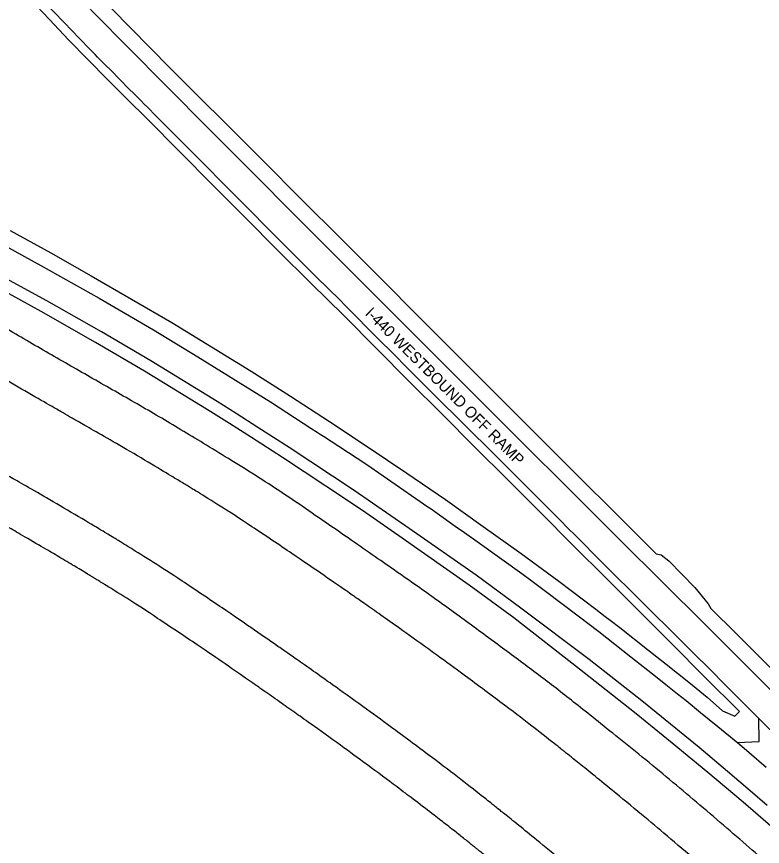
# Model space of a CAD drawing. Extents: x 1729281 to 1732101, y 650763 to 653805.
# Drawn here: x 1730660.8 to 1731062.7, y 652139.3 to 652586.3 of the extents above; entities that cross this region are included whole.
import ezdxf

# ---------------------------------------------------------------- set-up
doc = ezdxf.new("R2010")
doc.units = 0
for name, color, linetype in [('SURVEY - ROADSIDE BARRIERS with Text', 7, 'Continuous'), ('SURVEY - TRAFFIC CONTROL - Pavement Marking with Text', 7, 'Continuous'), ('SURVEY - TRANSPORTATION - Features', 7, 'Continuous'), ('SURVEY - TRANSPORTATION - Roads', 7, 'Continuous'), ('SURVEY - TRANSPORTATION - Roads Text', 7, 'Continuous')]:
    doc.layers.add(name, color=color, linetype=linetype)

msp = doc.modelspace()

# ---------------------------------------------------------------- linework, layer by layer
at = {"layer": 'SURVEY - ROADSIDE BARRIERS with Text'}
for points in [[(1730975.1, 652226.1), (1730964.18, 652234.73), (1730928.69, 652262.46), (1730904.57, 652280.1), (1730868.61, 652305.29), (1730848.9, 652318.94), (1730839.08, 652325.7), (1730804.14, 652348.81), (1730787.34, 652359.55), (1730775.57, 652367.08), (1730765.45, 652373.4), (1730729.72, 652395.29), (1730703.22, 652410.78), (1730673.94, 652427.43), (1730647.79, 652441.74)], [(1731071.12, 652146.74), (1731052.31, 652163.12), (1731033.25, 652179.2), (1731014.06, 652194.99), (1730994.61, 652210.7), (1730975.1, 652226.1)]]:
    msp.add_lwpolyline(points, dxfattribs=at)
at = {"layer": 'SURVEY - TRAFFIC CONTROL - Pavement Marking with Text'}
msp.add_lwpolyline([(1731049.05, 652195.35), (1731060.99, 652195.88), (1731060.77, 652208.25)], dxfattribs=at)
at = {"layer": 'SURVEY - TRANSPORTATION - Features'}
for points in [[(1730701.46, 652601.45), (1730722.34, 652580.03), (1730743.41, 652558.73), (1730764.61, 652537.57), (1730768.16, 652534.04), (1730793.21, 652508.89), (1730814.38, 652487.68), (1730835.6, 652466.49), (1730856.8, 652445.32), (1730878.03, 652424.11), (1730899.19, 652402.83), (1730920.41, 652381.64), (1730941.6, 652360.4), (1730962.88, 652339.27), (1730984.14, 652318.11), (1731005.4, 652296.96), (1731008.07, 652296.35)], [(1731047.73, 652209.41), (1731050.35, 652211.96), (1731031.53, 652230.73), (1731013.81, 652248.35), (1730996.17, 652266.06), (1730978.49, 652283.76), (1730960.75, 652301.37), (1730943.11, 652319.11), (1730925.41, 652336.72), (1730907.68, 652354.36), (1730890.14, 652372.17), (1730872.36, 652389.74), (1730854.71, 652407.49), (1730837.08, 652425.19), (1730819.29, 652442.68), (1730801.53, 652460.32), (1730783.88, 652478), (1730766.28, 652495.73), (1730748.75, 652513.52), (1730731.14, 652531.23), (1730720.44, 652541.73), (1730709.84, 652552.32), (1730699.34, 652563.01), (1730688.84, 652573.77), (1730678.59, 652584.69), (1730668.21, 652595.62)], [(1730657.24, 652471.12), (1730679.15, 652458.96), (1730700.91, 652446.66), (1730722.72, 652434.14), (1730744.45, 652421.45), (1730765.87, 652408.43), (1730787.1, 652395.25), (1730808.36, 652381.81), (1730829.42, 652368.2), (1730850.29, 652354.45), (1730871.15, 652340.34), (1730891.85, 652326.16), (1730912.26, 652311.72), (1730932.62, 652297.09), (1730952.92, 652282.17), (1730972.94, 652267.1), (1730977.98, 652263.09), (1730980.58, 652261.16), (1730985.79, 652257.15), (1731000.69, 652245.44)], [(1731008.07, 652296.35), (1731012.17, 652293.06), (1731026.29, 652278.76), (1731033.43, 652270.02)], [(1731033.43, 652270.02), (1731034.94, 652267.43), (1731048.46, 652253.94), (1731069.69, 652232.73), (1731090.91, 652211.51), (1731112.06, 652190.2), (1731133.28, 652168.97), (1731154.32, 652147.58), (1731175.37, 652126.2), (1731196.37, 652104.63), (1731217.28, 652083.07), (1731237.88, 652061.26), (1731258.4, 652039.18), (1731278.68, 652016.88), (1731284.06, 652009.86), (1731303.09, 651986.57), (1731322.55, 651963.65), (1731341.9, 651940.64), (1731361.11, 651917.48), (1731380.08, 651894.11), (1731398.72, 651870.57), (1731417.16, 651846.86), (1731435.47, 651822.97)], [(1731000.69, 652245.44), (1731010.72, 652237.52), (1731022.93, 652227.87), (1731032.92, 652219.72), (1731041.23, 652212.43), (1731047.73, 652209.41)]]:
    msp.add_lwpolyline(points, dxfattribs=at)
at = {"layer": 'SURVEY - TRANSPORTATION - Roads'}
for points in [[(1730693.2, 652597.85), (1730708.56, 652582.15), (1730715.58, 652575.04), (1730746.5, 652543.82), (1730759.18, 652531.06), (1730771.86, 652518.31), (1730793.02, 652497.08), (1730805.72, 652484.34), (1730831.15, 652458.88), (1730843.88, 652446.17), (1730863.71, 652426.41), (1730875.03, 652415.1), (1730899.04, 652391.04), (1730910.37, 652379.75), (1730935.76, 652354.33), (1730956.03, 652334.21), (1730971.98, 652318.3), (1730987.47, 652302.85), (1731007.33, 652283.11), (1731032.83, 652257.7), (1731045.57, 652244.98), (1731076.7, 652213.89), (1731092.24, 652198.32)], [(1731071.04, 652197.97), (1731062.56, 652206.46), (1731042.76, 652226.26), (1731034.27, 652234.74), (1731025.77, 652243.21), (1731017.24, 652251.66), (1730998.78, 652269.96), (1730976.37, 652292.33), (1730961.86, 652306.79), (1730957.88, 652310.75), (1730953.65, 652315.01), (1730930.88, 652337.88), (1730922.71, 652345.95), (1730897.7, 652370.82), (1730890.15, 652378.3), (1730871.71, 652396.62), (1730863.26, 652405.14), (1730856.22, 652412.24), (1730837.88, 652430.65), (1730835.05, 652433.48), (1730822.24, 652446.11), (1730813.69, 652454.53), (1730799.61, 652468.72), (1730782.71, 652485.73), (1730775.66, 652492.81), (1730758.93, 652509.61), (1730750.7, 652517.88), (1730742.28, 652526.35), (1730742.11, 652526.51), (1730735.25, 652533.42), (1730731.82, 652536.87), (1730729.04, 652539.66), (1730728.88, 652539.83), (1730728.8, 652539.91), (1730728.55, 652540.16), (1730728.39, 652540.32), (1730724.14, 652544.59), (1730721.33, 652547.42), (1730711.49, 652557.35), (1730708.68, 652560.19), (1730707.27, 652561.61), (1730704.46, 652564.45), (1730703.05, 652565.87), (1730701.65, 652567.29), (1730698.83, 652570.12), (1730696.05, 652572.99), (1730694.66, 652574.43), (1730690.5, 652578.73), (1730686.33, 652583.04), (1730675.22, 652594.51)], [(1730649.22, 652465.7), (1730673.76, 652452.23), (1730705.2, 652434.69), (1730734.58, 652417.59), (1730758.51, 652403.05), (1730784.01, 652387.26), (1730797.56, 652378.75), (1730819.41, 652364.67), (1730822.77, 652362.5), (1730824.45, 652361.42), (1730826.12, 652360.32), (1730834.48, 652354.83), (1730849.52, 652344.94), (1730875.87, 652326.79), (1730882.45, 652322.24), (1730884.09, 652321.1), (1730897.16, 652311.88), (1730902.06, 652308.42), (1730910.23, 652302.65), (1730932.95, 652286.29), (1730937.81, 652282.78), (1730945.81, 652276.78), (1730963.37, 652263.53), (1730974.48, 652255.01), (1730991.85, 652241.52), (1731005.94, 652230.32), (1731010.62, 652226.57), (1731016.87, 652221.57), (1731021.55, 652217.83), (1731029.3, 652211.51), (1731038.59, 652203.91), (1731049.42, 652195.05), (1731054.02, 652191.19), (1731055.54, 652189.89), (1731064.63, 652182.06)], [(1731065.18, 652161.42), (1731056.1, 652169.25), (1731043.89, 652179.6), (1731028.64, 652192.53), (1730997.61, 652217.76), (1730969.27, 652239.95), (1730932.57, 652267.67), (1730908.36, 652285.39), (1730872.32, 652310.62), (1730852.59, 652324.29), (1730842.71, 652331.09), (1730807.69, 652354.26), (1730790.84, 652365.03), (1730779.05, 652372.57), (1730768.87, 652378.93), (1730733.06, 652400.86), (1730706.47, 652416.41), (1730677.11, 652433.11), (1730650.89, 652447.45)]]:
    msp.add_lwpolyline(points, dxfattribs=at)
for points in [[(1731531.64, 651585.15), (1731524.94, 651594.88), (1731518.23, 651604.6), (1731511.53, 651614.33), (1731495.84, 651637.09), (1731479.61, 651659.46), (1731463.56, 651681.97), (1731448.09, 651703.66), (1731432.47, 651725.24), (1731416.68, 651746.7), (1731388.71, 651784.72), (1731359.2, 651821.53), (1731329.41, 651858.17), (1731313.35, 651877.92), (1731296.84, 651897.26), (1731279.99, 651916.35), (1731249.08, 651951.38), (1731217.44, 651985.64), (1731184.75, 652019.02), (1731165.49, 652038.69), (1731145.75, 652057.82), (1731125.51, 652076.48), (1731104.49, 652095.86), (1731083.19, 652114.88), (1731061.55, 652133.58), (1731032.69, 652158.51), (1731003.56, 652183.06), (1730973.77, 652206.88), (1730955.05, 652221.83), (1730936, 652236.31), (1730916.71, 652250.52), (1730895.37, 652266.24), (1730873.8, 652281.59), (1730852.02, 652296.7), (1730823.56, 652316.46), (1730794.97, 652335.97), (1730765.4, 652354.03), (1730742.02, 652368.29), (1730718.3, 652381.9), (1730694.53, 652395.48), (1730670.65, 652409.13), (1730646.99, 652423.18), (1730622.57, 652435.85), (1730604.25, 652445.36), (1730585.78, 652454.57), (1730567.34, 652463.85), (1730548.53, 652473.32), (1730529.72, 652482.79), (1730510.84, 652492.11), (1730492.28, 652501.28), (1730473.44, 652509.87), (1730454.35, 652517.88), (1730438.11, 652524.71), (1730421.85, 652531.5), (1730405.58, 652538.25)], [(1731511.88, 651571.53), (1731507.41, 651578.01), (1731500.71, 651587.73), (1731494.01, 651597.45), (1731491.64, 651600.89), (1731491.5, 651601.09), (1731491.23, 651601.49), (1731490.81, 651602.09), (1731489.85, 651603.49), (1731487.91, 651606.28), (1731486.24, 651608.67), (1731476.22, 651623.03), (1731467.12, 651635.76), (1731453.38, 651654.94), (1731448.78, 651661.35), (1731443.62, 651668.6), (1731443.05, 651669.39), (1731441.91, 651670.98), (1731440.2, 651673.38), (1731436.21, 651678.95), (1731423.65, 651696.46), (1731410.99, 651713.9), (1731399.98, 651728.9), (1731398.24, 651731.27), (1731397.07, 651732.85), (1731396.5, 651733.62), (1731393.62, 651737.53), (1731386.67, 651746.88), (1731379.63, 651756.18), (1731365.42, 651774.71), (1731355.8, 651786.99), (1731336.34, 651811.46), (1731326.51, 651823.66), (1731315.38, 651837.38), (1731313.52, 651839.66), (1731311.67, 651841.95), (1731310.43, 651843.47), (1731309.82, 651844.22), (1731306.76, 651847.97), (1731299.37, 651856.96), (1731286.88, 651871.82), (1731276.72, 651883.61), (1731266.49, 651895.37), (1731261.34, 651901.23), (1731245.82, 651918.75), (1731224.93, 651941.93), (1731198.32, 651970.43), (1731179.41, 651990.12), (1731171.24, 651998.51), (1731167.15, 652002.69), (1731165.8, 652004.07), (1731163.07, 652006.84), (1731150.8, 652019.25), (1731138.34, 652031.45), (1731121.48, 652047.47), (1731115.82, 652052.77), (1731108.69, 652059.35), (1731107.25, 652060.68), (1731104.37, 652063.32), (1731100.06, 652067.27), (1731084.2, 652081.72), (1731066.73, 652097.28), (1731052.02, 652110.08), (1731047.6, 652113.91), (1731046.13, 652115.19), (1731043.16, 652117.75), (1731035.75, 652124.14), (1731028.32, 652130.5), (1731010.45, 652145.7), (1730998.49, 652155.74), (1730980.44, 652170.62), (1730971.38, 652178.01), (1730962.28, 652185.34), (1730957.71, 652188.99), (1730956.2, 652190.19), (1730953.17, 652192.6), (1730939.49, 652203.41), (1730925.59, 652214.01), (1730900.64, 652232.62), (1730888.04, 652241.81), (1730869.01, 652255.44), (1730859.46, 652262.22), (1730849.87, 652268.95), (1730843.46, 652273.43), (1730840.26, 652275.65), (1730824.15, 652286.83), (1730811.28, 652295.68), (1730785.46, 652312.97), (1730772.5, 652321.4), (1730757.78, 652330.54), (1730756.14, 652331.55), (1730753.68, 652333.06), (1730752.86, 652333.56), (1730751.2, 652334.57), (1730747.06, 652337.09), (1730736.26, 652343.59), (1730719.49, 652353.47), (1730705.94, 652361.28), (1730695.75, 652367.13), (1730690.65, 652370.06), (1730685.53, 652372.98), (1730682.12, 652374.93), (1730680.39, 652375.92), (1730664.91, 652384.8), (1730651.37, 652392.7), (1730631.13, 652404.05), (1730624.39, 652407.75), (1730615.96, 652412.23), (1730614.27, 652413.11), (1730610.89, 652414.87), (1730609.15, 652415.77), (1730603.96, 652418.45), (1730600.5, 652420.23), (1730590.07, 652425.56), (1730583.08, 652429.08), (1730569.07, 652436.14), (1730562.03, 652439.66), (1730540.91, 652450.27), (1730526.87, 652457.34), (1730509.33, 652466.07), (1730505.83, 652467.82), (1730501.44, 652469.99), (1730500.56, 652470.42), (1730498.83, 652471.28), (1730496.24, 652472.55), (1730486.72, 652477.19), (1730478.03, 652481.28), (1730464.07, 652487.63), (1730457.06, 652490.71), (1730449.14, 652494.05), (1730447.82, 652494.61), (1730446.28, 652495.25), (1730445.62, 652495.52), (1730445.18, 652495.71), (1730444.95, 652495.8), (1730442.91, 652496.65), (1730437.45, 652498.91), (1730423.38, 652504.74), (1730411.12, 652509.82), (1730399.69, 652514.48)], [(1731474.27, 651542.24), (1731469.8, 651548.72), (1731463.1, 651558.44), (1731456.4, 651568.16), (1731454.02, 651571.6), (1731453.89, 651571.8), (1731453.61, 651572.2), (1731453.2, 651572.8), (1731452.23, 651574.19), (1731450.3, 651576.99), (1731448.63, 651579.38), (1731438.6, 651593.74), (1731429.5, 651606.46), (1731415.76, 651625.65), (1731411.17, 651632.06), (1731406, 651639.3), (1731405.44, 651640.1), (1731404.3, 651641.69), (1731402.59, 651644.08), (1731398.6, 651649.66), (1731386.03, 651667.17), (1731373.37, 651684.6), (1731362.36, 651699.61), (1731360.62, 651701.98), (1731359.46, 651703.55), (1731358.89, 651704.33), (1731356.01, 651708.24), (1731349.06, 651717.59), (1731342.01, 651726.88), (1731327.81, 651745.42), (1731318.18, 651757.7), (1731298.73, 651782.17), (1731288.89, 651794.37), (1731277.77, 651808.08), (1731275.91, 651810.37), (1731274.05, 651812.66), (1731272.81, 651814.18), (1731272.21, 651814.93), (1731269.14, 651818.68), (1731261.75, 651827.67), (1731249.26, 651842.53), (1731239.1, 651854.32), (1731228.88, 651866.08), (1731223.73, 651871.94), (1731208.21, 651889.46), (1731187.32, 651912.63), (1731160.7, 651941.14), (1731141.79, 651960.83), (1731133.63, 651969.22), (1731129.54, 651973.4), (1731128.18, 651974.78), (1731125.46, 651977.54), (1731113.19, 651989.96), (1731100.72, 652002.15), (1731083.86, 652018.18), (1731078.2, 652023.48), (1731071.07, 652030.06), (1731069.63, 652031.38), (1731066.76, 652034.02), (1731062.45, 652037.98), (1731046.58, 652052.43), (1731029.12, 652067.98), (1731014.41, 652080.79), (1731009.99, 652084.62), (1731008.51, 652085.9), (1731005.55, 652088.46), (1730998.13, 652094.85), (1730990.7, 652101.21), (1730972.84, 652116.41), (1730960.88, 652126.44), (1730942.82, 652141.33), (1730933.77, 652148.72), (1730924.66, 652156.04), (1730920.1, 652159.69), (1730918.59, 652160.9), (1730915.55, 652163.3), (1730901.87, 652174.12), (1730887.98, 652184.72), (1730863.02, 652203.32), (1730850.42, 652212.51), (1730831.4, 652226.15), (1730821.85, 652232.93), (1730812.25, 652239.66), (1730805.85, 652244.13), (1730802.65, 652246.36), (1730786.53, 652257.54), (1730773.67, 652266.39), (1730747.85, 652283.68), (1730734.89, 652292.11), (1730720.16, 652301.25), (1730718.53, 652302.26), (1730716.07, 652303.77), (1730715.25, 652304.27), (1730713.59, 652305.28), (1730709.45, 652307.79), (1730698.64, 652314.3), (1730681.87, 652324.17), (1730668.33, 652331.99), (1730658.14, 652337.84), (1730653.03, 652340.77), (1730647.92, 652343.69), (1730644.5, 652345.64), (1730642.77, 652346.63), (1730627.29, 652355.51), (1730613.76, 652363.4), (1730593.52, 652374.75), (1730586.78, 652378.46), (1730578.35, 652382.93), (1730576.66, 652383.82), (1730573.28, 652385.58), (1730571.54, 652386.48), (1730566.35, 652389.16), (1730562.88, 652390.94), (1730552.45, 652396.26), (1730545.47, 652399.79), (1730531.45, 652406.84), (1730524.42, 652410.37), (1730503.29, 652420.98), (1730489.26, 652428.05), (1730471.72, 652436.78), (1730468.21, 652438.52), (1730463.83, 652440.7), (1730462.95, 652441.13), (1730461.22, 652441.98), (1730458.63, 652443.26), (1730449.11, 652447.9), (1730440.41, 652451.99), (1730426.45, 652458.34), (1730419.45, 652461.42), (1730411.53, 652464.76), (1730410.21, 652465.31), (1730408.67, 652465.96), (1730408.01, 652466.23), (1730407.57, 652466.41), (1730407.34, 652466.51), (1730405.29, 652467.35), (1730399.84, 652469.61), (1730394.3, 652471.91), (1730390.59, 652473.45), (1730390.5, 652473.48)], [(1731454.51, 651528.62), (1731450.04, 651535.1), (1731445.57, 651541.58), (1731439.99, 651549.68), (1731438.31, 651552.11), (1731436.36, 651554.94), (1731435.38, 651556.36), (1731434.96, 651556.97), (1731434.68, 651557.37), (1731434.54, 651557.58), (1731434.13, 651558.18), (1731433.86, 651558.56), (1731433.32, 651559.34), (1731433.05, 651559.74), (1731432.22, 651560.93), (1731431.67, 651561.72), (1731430.04, 651564.08), (1731428.94, 651565.66), (1731423.44, 651573.54), (1731418.97, 651579.86), (1731412.21, 651589.36), (1731409.95, 651592.54), (1731405.4, 651598.9), (1731403.12, 651602.08), (1731398.54, 651608.48), (1731395.1, 651613.28), (1731391.07, 651618.92), (1731389.05, 651621.74), (1731388.19, 651622.95), (1731387.61, 651623.76), (1731387.32, 651624.16), (1731385.89, 651626.17), (1731384.77, 651627.73), (1731382.5, 651630.92), (1731381.36, 651632.51), (1731377.95, 651637.26), (1731375.68, 651640.43), (1731364.29, 651656.26), (1731355.12, 651668.89), (1731344.75, 651683.04), (1731343.6, 651684.62), (1731342.15, 651686.58), (1731341.72, 651687.17), (1731341.29, 651687.76), (1731341, 651688.15), (1731340.85, 651688.35), (1731340.42, 651688.93), (1731340.14, 651689.32), (1731339.71, 651689.9), (1731339.57, 651690.09), (1731339.28, 651690.48), (1731339.14, 651690.68), (1731336.73, 651693.95), (1731334.44, 651697.02), (1731327.55, 651706.23), (1731322.91, 651712.35), (1731308.86, 651730.68), (1731299.33, 651742.85), (1731280.01, 651767.15), (1731270.23, 651779.29), (1731259.13, 651792.96), (1731257.9, 651794.48), (1731256.35, 651796.38), (1731255.89, 651796.95), (1731255.43, 651797.52), (1731255.12, 651797.9), (1731254.96, 651798.09), (1731254.51, 651798.65), (1731254.2, 651799.02), (1731253.75, 651799.58), (1731253.6, 651799.76), (1731253.3, 651800.14), (1731253.14, 651800.33), (1731250.58, 651803.46), (1731248.16, 651806.41), (1731240.85, 651815.24), (1731235.92, 651821.1), (1731225.97, 651832.8), (1731220.95, 651838.63), (1731210.82, 651850.27), (1731205.72, 651856.08), (1731190.33, 651873.44), (1731169.63, 651896.41), (1731143.26, 651924.65), (1731127.21, 651941.37), (1731120.49, 651948.3), (1731118.47, 651950.38), (1731116.11, 651952.8), (1731115.1, 651953.84), (1731114.43, 651954.52), (1731114.09, 651954.87), (1731113.07, 651955.91), (1731112.39, 651956.6), (1731111.39, 651957.63), (1731111.05, 651957.97), (1731110.39, 651958.65), (1731110.06, 651958.98), (1731108.38, 651960.68), (1731096.3, 651972.91), (1731084.02, 651984.92), (1731070.18, 651998.07), (1731066.01, 652002), (1731061.13, 652006.56), (1731059.03, 652008.51), (1731057.62, 652009.81), (1731056.92, 652010.46), (1731055.52, 652011.75), (1731054.81, 652012.41), (1731053.75, 652013.39), (1731053.39, 652013.72), (1731052.67, 652014.37), (1731052.31, 652014.71), (1731050.54, 652016.34), (1731049.11, 652017.64), (1731044.83, 652021.56), (1731030.54, 652034.57), (1731016.12, 652047.42), (1731003.03, 652058.87), (1731000.85, 652060.77), (1730998.3, 652062.99), (1730997.21, 652063.94), (1730996.48, 652064.57), (1730996.12, 652064.88), (1730995.01, 652065.84), (1730993.91, 652066.79), (1730992.63, 652067.9), (1730992.08, 652068.37), (1730991.72, 652068.69), (1730991.54, 652068.84), (1730989.87, 652070.28), (1730988.39, 652071.55), (1730981.02, 652077.91), (1730975.11, 652082.96), (1730957.37, 652098.06), (1730945.5, 652108.02), (1730927.62, 652122.76), (1730921.64, 652127.64), (1730914.14, 652133.7), (1730911.89, 652135.52), (1730909.64, 652137.32), (1730908.13, 652138.53), (1730907.38, 652139.13), (1730905.13, 652140.93), (1730903.65, 652142.11), (1730900.66, 652144.48), (1730899.17, 652145.67), (1730891.67, 652151.56), (1730885.63, 652156.25), (1730873.45, 652165.56), (1730867.32, 652170.18), (1730848.81, 652183.98), (1730836.33, 652193.09), (1730817.47, 652206.6), (1730811.16, 652211.08), (1730801.66, 652217.78), (1730798.48, 652220), (1730793.72, 652223.33), (1730792.13, 652224.44), (1730788.94, 652226.66), (1730787.35, 652227.77), (1730772.9, 652237.79), (1730760.15, 652246.56), (1730734.67, 652263.62), (1730721.94, 652271.9), (1730708.35, 652280.34), (1730707.55, 652280.83), (1730705.95, 652281.82), (1730705.15, 652282.31), (1730703.95, 652283.04), (1730703.55, 652283.29), (1730702.94, 652283.66), (1730702.63, 652283.85), (1730702.33, 652284.03), (1730702.12, 652284.16), (1730702.01, 652284.23), (1730701.11, 652284.78), (1730700.3, 652285.27), (1730696.22, 652287.75), (1730692.94, 652289.72), (1730683.07, 652295.62), (1730676.43, 652299.52), (1730663.07, 652307.31), (1730656.35, 652311.2), (1730646.2, 652317.02), (1730642.81, 652318.96), (1730637.71, 652321.88), (1730636.01, 652322.85), (1730633.45, 652324.32), (1730632.59, 652324.81), (1730630.85, 652325.8), (1730629.98, 652326.3), (1730615.25, 652334.75), (1730601.78, 652342.6), (1730581.89, 652353.75), (1730575.32, 652357.37), (1730567.14, 652361.71), (1730565.51, 652362.57), (1730563.06, 652363.85), (1730562.22, 652364.28), (1730560.95, 652364.94), (1730560.31, 652365.27), (1730559.66, 652365.61), (1730559.23, 652365.83), (1730559.01, 652365.94), (1730555.38, 652367.82), (1730551.94, 652369.58), (1730541.6, 652374.86), (1730534.66, 652378.36), (1730520.69, 652385.39), (1730513.66, 652388.92), (1730492.5, 652399.54), (1730478.49, 652406.6), (1730462.78, 652414.42), (1730460.16, 652415.73), (1730457.11, 652417.24), (1730455.8, 652417.89), (1730454.93, 652418.32), (1730454.49, 652418.54), (1730453.62, 652418.97), (1730452.97, 652419.29), (1730452.33, 652419.61), (1730451.9, 652419.82), (1730451.69, 652419.92), (1730450.61, 652420.46), (1730449.75, 652420.88), (1730447.23, 652422.12), (1730445.54, 652422.94), (1730437.07, 652427.03), (1730430.29, 652430.22), (1730416.7, 652436.41), (1730409.89, 652439.4), (1730402.22, 652442.64), (1730401.37, 652443), (1730400.09, 652443.53), (1730399.66, 652443.71), (1730398.79, 652444.07), (1730398.38, 652444.24), (1730396.11, 652445.18), (1730394.29, 652445.94), (1730390.08, 652447.68), (1730387.7, 652448.67), (1730385.31, 652449.66)]]:
    msp.add_open_spline(points, degree=3, dxfattribs=at)

# ---------------------------------------------------------------- texts
at = {"layer": 'SURVEY - TRANSPORTATION - Roads Text'}
msp.add_text('I-440 WESTBOUND OFF RAMP', height=6, rotation=315.1995, dxfattribs=at).set_placement((1730848.17, 652426.03))
msp.add_text('I-440 WESTBOUND OFF RAMP', height=6, rotation=315.1995, dxfattribs=at).set_placement((1730848.17, 652426.03))

doc.saveas('drawing.dxf')
